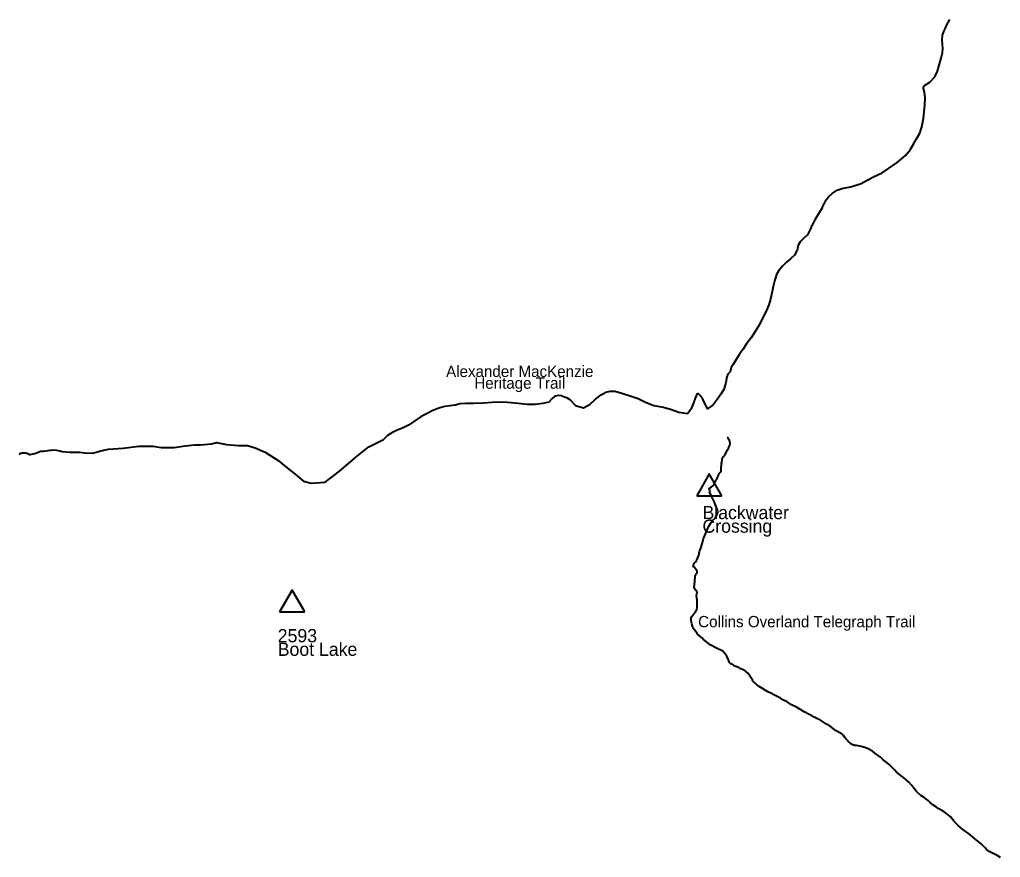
# Model space of a CAD drawing. Extents: x 322505 to 642419, y 5806860 to 5919753.
# Drawn here: x 472235 to 498213, y 5894520 to 5916713 of the extents above; entities that cross this region are included whole.
import ezdxf
from ezdxf.enums import TextEntityAlignment as Align

# ---------------------------------------------------------------- set-up
doc = ezdxf.new("R2010")
doc.units = 0
doc.header["$LTSCALE"] = 140
for name, color, linetype, lineweight in [('1', 7, 'Continuous', 40), ('2', 7, 'Continuous', 40), ('4', 7, 'Continuous', 40), ('6', 7, 'Continuous', 40)]:
    doc.layers.add(name, color=color, linetype=linetype, lineweight=lineweight)

msp = doc.modelspace()

# ---------------------------------------------------------------- linework, layer by layer
at = {"layer": '1'}
msp.add_line((479122.1, 5901020.4), (479787.5, 5901020.4), dxfattribs=at)
msp.add_lwpolyline([(479787.5, 5901020.4), (479454.8, 5901596.6), (479122.1, 5901020.4)], dxfattribs=at)
at = {"layer": '2'}
msp.add_line((490169.8, 5904099.9), (490835.2, 5904099.9), dxfattribs=at)
msp.add_lwpolyline([(490835.2, 5904099.9), (490502.5, 5904676.1), (490169.8, 5904099.9)], dxfattribs=at)
at = {"layer": '4'}
for p, q in [((490983.7, 5905652.5), (490983.7, 5905652.5)), ((490506.1, 5904268.1), (490502, 5904275)), ((490512.8, 5904256.8), (490506.1, 5904268.1)), ((490143, 5902162.7), (490133, 5902180)), ((490120.9, 5901841.6), (490125.6, 5901964.6)), ((490125.6, 5901964.6), (490125.7, 5901967.3)), ((490125.7, 5901967.3), (490126.2, 5901979.3)), ((490185.1, 5901299.9), (490181, 5901346.2)), ((490182.8, 5901174.6), (490185, 5901240.4)), ((490029.2, 5900893.3), (490089.6, 5900973)), ((490063.1, 5900617.4), (490062.9, 5900617.8)), ((490063.9, 5900616.3), (490063.1, 5900617.4)), ((490087.7, 5900582.9), (490063.9, 5900616.3)), ((490180.4, 5900452.8), (490087.7, 5900582.9)), ((490296.3, 5900346), (490291.2, 5900350.6)), ((490318.8, 5900325.8), (490296.3, 5900346)), ((491715.8, 5899134.6), (491712.5, 5899137.5)), ((491756.1, 5899099.5), (491715.8, 5899134.6)), ((491756.1, 5899099.5), (491756.1, 5899099.5)), ((494032.2, 5897773.8), (494022, 5897779.8)), ((494032.4, 5897773.6), (494032.2, 5897773.8)), ((494032.2, 5897773.8), (494032.2, 5897773.8)), ((494355, 5897485.4), (494355, 5897485.4)), ((495709.7, 5896586.2), (495709.7, 5896586.2)), ((495709.7, 5896586.2), (495709.7, 5896586.2)), ((495709.7, 5896586.2), (495709.7, 5896586.2)), ((495709.7, 5896586.2), (495709.7, 5896586.2)), ((495709.7, 5896586.2), (495709.7, 5896586.2)), ((495950.6, 5896321.4), (495949.9, 5896322.4)), ((495950.6, 5896321.4), (495950.6, 5896321.4)), ((496413.4, 5895921.7), (496411, 5895924)), ((496411, 5895924), (496411, 5895924)), ((496413.6, 5895921.6), (496413.4, 5895921.7))]:
    msp.add_line(p, q, dxfattribs=at)
for points in [[(491049, 5905450), (491052, 5905457), (491054, 5905467), (491056, 5905469), (491056, 5905483), (491054, 5905507), (491051, 5905521), (491049, 5905529), (491047, 5905537), (491042, 5905561), (491038, 5905568), (491036, 5905576), (491032, 5905582), (491020, 5905603), (491014, 5905611), (491000, 5905631), (490995, 5905639), (490991, 5905647), (490984, 5905652), (490983.7, 5905652.5)], [(490502, 5904275), (490501, 5904277), (490502, 5904286), (490504, 5904294), (490507, 5904299), (490514, 5904306), (490536, 5904320), (490542, 5904324), (490563, 5904340), (490585, 5904353), (490600, 5904364), (490617, 5904386), (490622, 5904392), (490634, 5904411), (490645, 5904433), (490653, 5904450), (490663, 5904472), (490666, 5904480), (490680, 5904500), (490692, 5904525), (490700, 5904541), (490715, 5904565), (490724, 5904579), (490733, 5904598), (490738, 5904616), (490744, 5904635), (490750, 5904652), (490756, 5904666), (490763, 5904681), (490777, 5904699), (490794, 5904717), (490812, 5904735), (490816, 5904750), (490816, 5904771), (490819, 5904795), (490819, 5904813), (490818, 5904830), (490818, 5904846), (490820, 5904864), (490822, 5904882), (490823, 5904892), (490827, 5904916), (490828, 5904940), (490829, 5904954), (490833, 5904978), (490837, 5905001), (490839, 5905014), (490841, 5905027), (490842, 5905050), (490845, 5905066), (490847, 5905076), (490855, 5905094), (490860, 5905104), (490870, 5905121), (490883, 5905138), (490889, 5905147), (490894, 5905152), (490896, 5905155), (490899, 5905160), (490914, 5905180), (490920, 5905188), (490934, 5905211), (490943, 5905233), (490946, 5905240), (490957, 5905261), (490969, 5905286), (490984, 5905311), (490989, 5905321), (491000, 5905336), (491012, 5905356), (491022, 5905378), (491031, 5905401), (491041, 5905423), (491045, 5905431), (491049, 5905450)], [(490508.7, 5904201.4), (490513, 5904206), (490517, 5904213), (490519, 5904224), (490520, 5904236), (490520, 5904244), (490518, 5904248), (490512.8, 5904256.8)], [(490623.1, 5903961.5), (490571.6, 5904074.7), (490508.7, 5904201.4), (490508.7, 5904201.4)], [(490168.3, 5902372.8), (490211.1, 5902485), (490211.1, 5902485.5), (490223.2, 5902525.7), (490247.1, 5902619.7), (490280.6, 5902711.2), (490309.5, 5902801.1), (490331.3, 5902884.5), (490351.1, 5902964.3), (490380.5, 5903048.1), (490429.3, 5903149.3), (490454.6, 5903217.4), (490494.2, 5903298.2), (490549.1, 5903389.2), (490588.7, 5903447.2), (490669, 5903518.9), (490720.3, 5903625.6), (490730.9, 5903676.4), (490710, 5903752.1), (490680, 5903826.8), (490637.7, 5903929.4), (490623.1, 5903961.5)], [(490142, 5902352), (490146, 5902355), (490167, 5902371), (490168.3, 5902372.8)], [(490076, 5902216), (490082, 5902239), (490083, 5902248), (490089, 5902270), (490093, 5902288), (490098, 5902307), (490099, 5902309)], [(490133, 5902180), (490118, 5902195), (490096, 5902209), (490089, 5902212), (490076, 5902216)], [(490099, 5902309), (490104, 5902313), (490109, 5902318), (490115, 5902325), (490139, 5902350), (490142, 5902352)], [(490126.2, 5901979.3), (490133, 5901991), (490148, 5902011), (490158, 5902027), (490172, 5902048), (490179, 5902062), (490184, 5902081), (490185, 5902101), (490178, 5902115), (490172, 5902122), (490152, 5902147), (490143, 5902162.7)], [(490181, 5901346.2), (490177, 5901390.9), (490168.3, 5901461.3), (490174.6, 5901498.5), (490184.1, 5901530.1), (490183.3, 5901552.2), (490164.3, 5901575.2), (490128.6, 5901616.3), (490104.9, 5901676.4), (490112, 5901736.5), (490120.7, 5901837.7), (490120.9, 5901841.6)], [(490089.6, 5900973), (490133.4, 5901018.5), (490158.3, 5901062.1)], [(490158.3, 5901062.1), (490169.1, 5901081), (490181.1, 5901157.1)], [(490181.1, 5901157.1), (490182.5, 5901166.4), (490182.8, 5901174.6)], [(490185, 5901240.4), (490185.7, 5901292.9), (490185.1, 5901299.9)], [(490039.4, 5900708.2), (490031.2, 5900741), (490019.3, 5900824), (490019.3, 5900874.6), (490029.2, 5900893.3)], [(490062.9, 5900617.8), (490054.2, 5900649.2), (490039.4, 5900708.2)], [(490291.2, 5900350.6), (490185.8, 5900445.2), (490180.4, 5900452.8)], [(490904.2, 5899933.4), (490865.3, 5899981.2), (490690.5, 5900065.5), (490524.9, 5900153.9), (490343.7, 5900303.4), (490318.8, 5900325.8)], [(491012.5, 5899752.7), (490968.8, 5899854.2), (490904.2, 5899933.4)], [(491205.5, 5899577.2), (491182.9, 5899587.8), (491155.2, 5899600.9), (491141.9, 5899608.5), (491129.4, 5899617.6), (491104.5, 5899635.7), (491090.4, 5899641.7), (491075.6, 5899646.6), (491066.4, 5899651.5), (491053.8, 5899661.9), (491043, 5899674), (491037.3, 5899682.9), (491031.5, 5899695.8), (491022, 5899724.2), (491012.5, 5899752.7)], [(491418.5, 5899479.5), (491381.9, 5899495.7), (491339.1, 5899514.7), (491315.3, 5899525.7), (491291.6, 5899536.8), (491251.1, 5899555.8), (491210.7, 5899574.8), (491205.5, 5899577.2)], [(491517.5, 5899403.7), (491503.2, 5899419), (491483, 5899437.9), (491461.4, 5899455), (491446.2, 5899465.2), (491424.7, 5899476.7), (491418.5, 5899479.5)], [(491712.5, 5899137.5), (491703, 5899143.8), (491693.5, 5899150.1), (491687.2, 5899155.3), (491681.9, 5899161.6), (491672.9, 5899175.4), (491658.5, 5899199.1), (491644.3, 5899222.9), (491626.9, 5899252.9), (491609.5, 5899283), (491597, 5899302.6), (491583.6, 5899321.6), (491555.6, 5899358.9), (491530.5, 5899389.8), (491517.5, 5899403.7)], [(492387.5, 5898735.4), (492339.3, 5898765.4), (492232.5, 5898820.7), (492131.8, 5898874), (492057.1, 5898909), (491983.8, 5898949.1), (491910.6, 5898994.2), (491827.2, 5899044.5), (491777.4, 5899081), (491756.1, 5899099.5)], [(493262.6, 5898246.2), (493205.8, 5898275.8), (493131.6, 5898315.4), (493017.7, 5898375.8), (492898.7, 5898445.8), (492815.3, 5898497.5), (492677.5, 5898563), (492563, 5898639.1), (492451.2, 5898695.9), (492387.5, 5898735.4)], [(494022, 5897779.8), (493863.4, 5897873.9), (493788.1, 5897934.3), (493705.7, 5897992.7), (493606.6, 5898048), (493531.3, 5898103.8), (493444.8, 5898157.1), (493366.5, 5898189.1), (493319.7, 5898216.5), (493262.6, 5898246.2)], [(494182.8, 5897593), (494167.8, 5897617.1), (494129.1, 5897654.5), (494086.6, 5897706.2), (494057.7, 5897751.1), (494032.4, 5897773.6)], [(494274.6, 5897517.8), (494255, 5897528), (494233, 5897547), (494219, 5897555), (494213, 5897560), (494209, 5897566), (494189, 5897583), (494182.8, 5897593)], [(494355, 5897485.4), (494305.8, 5897501.5), (494274.6, 5897517.8)], [(495709.7, 5896586.2), (495703, 5896592.7), (495621, 5896655.8), (495538.9, 5896711.2), (495462, 5896777.9), (495413.6, 5896827.9), (495298.4, 5896948.2), (495256.3, 5896993), (495179.3, 5897050.9), (495107.2, 5897107.5), (495039.1, 5897176.7), (494884.9, 5897281.1), (494877.5, 5897293.8), (494821.6, 5897337.5), (494708.2, 5897394.7), (494620.9, 5897429.9), (494529.8, 5897458.9), (494399.8, 5897483.4), (494355, 5897485.4)], [(495922, 5896356.7), (495866.5, 5896422.5), (495777.4, 5896519.7), (495709.7, 5896586.2)], [(495949.9, 5896322.4), (495943.2, 5896331.7), (495922, 5896356.7)], [(496411, 5895924), (496357.7, 5895972.3), (496303.2, 5896026.1), (496192.6, 5896107.2), (496109.2, 5896161.4), (495992.6, 5896262.8), (495950.6, 5896321.4)], [(498213.4, 5894519.7), (498169.9, 5894541.4), (498089, 5894584.2), (498000.5, 5894628.4), (497912.1, 5894677.6), (497845, 5894729), (497807.9, 5894772.5), (497747.2, 5894836.5), (497717.5, 5894869.7), (497659.1, 5894911), (497572.1, 5894980.4), (497462.9, 5895070.3), (497392.2, 5895134.4), (497223.1, 5895254.2), (497100.2, 5895359.5), (497054.4, 5895408.1), (496992.4, 5895469.6), (496893.5, 5895592.3), (496829, 5895647.5), (496724.6, 5895724.7), (496681.1, 5895755.6), (496565.2, 5895816.6), (496525.5, 5895852.5), (496428.4, 5895908.1), (496413.6, 5895921.6)]]:
    msp.add_lwpolyline(points, dxfattribs=at)
at = {"layer": '6'}
for points in [[(493490.7, 5911725.3), (493602.3, 5911936.1), (493665.6, 5912026.2), (493760.8, 5912109.4), (493893.3, 5912192), (494047.3, 5912246.7), (494253, 5912286.9), (494527.3, 5912370.2), (494684.9, 5912459.7), (494866.9, 5912553.1), (495077.7, 5912653.3), (495251.1, 5912769.8), (495477.5, 5912930.1), (495700.2, 5913116.9), (495827.3, 5913264.9), (495923.7, 5913434.6), (495993.3, 5913558.3), (496079.4, 5913704.7), (496135.9, 5913873.7), (496176.1, 5914094.8), (496195.7, 5914272.8), (496216.5, 5914446.1), (496225, 5914636.8), (496202.6, 5914792.1), (496175.7, 5914888.4), (496176.3, 5914931.2), (496207, 5914967.9), (496341.7, 5915052.7), (496480, 5915201.3), (496545.3, 5915347.7), (496593.4, 5915505), (496643.7, 5915693.8), (496680.1, 5915837.5), (496690.6, 5915944.2), (496683.9, 5916055.8), (496674.4, 5916174.8), (496683.4, 5916299.2), (496714.3, 5916398.9), (496750.9, 5916469.8), (496795.9, 5916570.8), (496876.7, 5916713.3)], [(493490.7, 5911725.3), (493294.2, 5911411.8), (493262.2, 5911338.7), (493222.9, 5911257.7), (493177.6, 5911153.2), (493102.6, 5911012.2), (493006.1, 5910925.9), (492908.6, 5910829.5), (492859.5, 5910735.7), (492830.3, 5910606.9), (492763.8, 5910475.7), (492651, 5910377.4), (492550.4, 5910285.7), (492442.4, 5910186.2), (492343.8, 5910068.2), (492283.4, 5909957.6), (492229, 5909780.7), (492198.1, 5909641.9), (492162.3, 5909470.3), (492126, 5909311.3), (492083.9, 5909157.1), (492007.2, 5908986.7), (491924.6, 5908824.4), (491829.4, 5908640.7), (491719.7, 5908450.4), (491608.9, 5908286.3), (491489.5, 5908121.3), (491389.2, 5907973.1), (491300, 5907848.8), (491214.1, 5907712.1), (491132.6, 5907581.2), (491079, 5907496.9), (491051.5, 5907384.7), (490994.4, 5907320.7), (490965, 5907248.4), (490944.9, 5907096.5), (490884, 5906917.2), (490810.8, 5906787.9), (490738.8, 5906686.1), (490654.3, 5906581.2), (490603.5, 5906512.6), (490455.7, 5906403), (490329.7, 5906660), (490249.9, 5906767.7), (490195.8, 5906816.5)], [(486596.3, 5906744.8), (486637.7, 5906731.9), (486719.9, 5906699.4), (486806, 5906649), (486960.8, 5906493.9), (487173.6, 5906424.7), (487346.9, 5906522), (487488.7, 5906655.7), (487642.7, 5906770), (487762.7, 5906842.9), (487875.9, 5906874.5), (488007.5, 5906871.4), (488213.4, 5906810.6), (488434.7, 5906741.8), (488618.1, 5906674.5), (488814.4, 5906581.2), (489032.5, 5906493.6), (489289.7, 5906449.7), (489502.8, 5906387.8), (489695.3, 5906311.8), (489922.2, 5906277.3), (490041, 5906426.7), (490096.1, 5906564.1), (490135.1, 5906685.7), (490188.4, 5906807.6), (490195.8, 5906816.5)], [(486596.3, 5906744.8), (486517.7, 5906757.7), (486407.9, 5906735.7), (486342.1, 5906680.1), (486252.7, 5906579.8), (486091.8, 5906542.2), (485886.6, 5906512.9), (485673.3, 5906516), (485437.6, 5906543.9), (485156.9, 5906570), (484962, 5906575.4), (484753.6, 5906572.2), (484515.9, 5906556.6), (484266.5, 5906541.9), (484047.4, 5906547.6), (483891.5, 5906537.5), (483781.1, 5906502.5), (483629.5, 5906483.6), (483495.7, 5906464.3), (483362.5, 5906427.7), (483178.1, 5906357.8), (483026.1, 5906282.1), (482870.4, 5906197.9), (482702.9, 5906082.5), (482537.8, 5905973.4), (482392.2, 5905899.4), (482219.7, 5905825.7), (482093.6, 5905763.3), (481977.5, 5905696.8), (481886.5, 5905601.7), (481869.8, 5905587.7)], [(473350.2, 5905274.4), (473357.4, 5905271.5), (473364.8, 5905269.2), (473572.3, 5905251), (473829.6, 5905256.1), (474018, 5905228.4), (474202.4, 5905233.6), (474387.4, 5905286.4), (474588.6, 5905334.3), (474978.5, 5905364.4), (475395, 5905411.5), (475773.4, 5905411.1), (475984.4, 5905379.3), (476327.8, 5905381.5), (476615.5, 5905420.5), (476874.4, 5905445.3), (477030.2, 5905445.1), (477317.1, 5905479.1), (477451.5, 5905509.3), (477715, 5905461), (478034.2, 5905428.7), (478270.4, 5905430.1), (478470.4, 5905371.4), (478734.5, 5905256.6), (479084.7, 5905033.9), (479331.5, 5904828.9), (479535.1, 5904672.2), (479755, 5904484.1), (479955, 5904434.3), (480330.1, 5904463), (480710.4, 5904751), (481182.5, 5905153.1), (481480.9, 5905393.2), (481858.8, 5905581.3), (481869.8, 5905587.7)], [(472488.4, 5905195.2), (472455, 5905207), (472435, 5905218), (472411, 5905222), (472390, 5905226), (472370, 5905228), (472349, 5905228), (472326, 5905227), (472305, 5905226), (472301, 5905226), (472279, 5905222), (472258, 5905217), (472239, 5905209), (472217, 5905195)], [(472488.4, 5905195.2), (472518.3, 5905195.2), (472548.5, 5905200.4), (472587.6, 5905206.5), (472634.7, 5905218.5), (472678.2, 5905233.9), (472729.8, 5905256.4), (472758.2, 5905269.7), (472797.2, 5905277.5), (472866.5, 5905281.2), (472925.6, 5905287.3), (472990.1, 5905298), (473038.8, 5905304.7), (473082.2, 5905309.4), (473137.5, 5905313.2), (473214.1, 5905305.6), (473257.6, 5905295.8), (473301.2, 5905287.5), (473322.7, 5905282.3), (473339.9, 5905279.6), (473350.2, 5905274.4)]]:
    msp.add_lwpolyline(points, dxfattribs=at)

# ---------------------------------------------------------------- texts
at = {"layer": '1'}
for s, p in [('2593', (479072, 5900218.1)), ('Boot Lake', (479072, 5899858.1))]:
    msp.add_text(s, height=350, dxfattribs=at).set_placement(p)
at = {"layer": '2'}
for s, p in [('Blackwater', (490322.9, 5903480.5)), ('Crossing', (490322.9, 5903120.5))]:
    msp.add_text(s, height=350, dxfattribs=at).set_placement(p)
at = {"layer": '4'}
msp.add_text('Collins Overland Telegraph Trail', height=300, dxfattribs=at).set_placement((490208.4, 5900615.5))
at = {"layer": '6'}
for s, p in [('Alexander MacKenzie', (485482.5, 5907245)), ('Heritage Trail', (485482.5, 5906935))]:
    msp.add_text(s, height=300, dxfattribs=at).set_placement(p, align=Align.CENTER)

doc.saveas('drawing.dxf')
